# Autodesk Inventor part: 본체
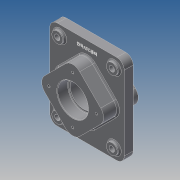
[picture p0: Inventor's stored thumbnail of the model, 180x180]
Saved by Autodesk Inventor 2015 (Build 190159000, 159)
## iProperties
Created: 2026-07
Part Number: 본체
Material: 일반
Document SubType Name: Modeling
Designer: USER
Density: 1 g/cm^3
Appearance: 기본값
Author: USER
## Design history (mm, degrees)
sketch "스케치1"
  geometry: L1 (75, 90)-(-75, 90); L2 (-75, 90)-(-75, -90); L3 (-75, -90)-(75, -90); L4 (75, -90)-(75, 90); L5 (75, 90)-(-75, -90); L6 (-75, 90)-(75, -90); 1 further point
  constraints: 12 end point, 2 midpoint, 2 parallel, 1 horizontal, 1 perpendicular
  dimensions: "d0" = 150 distance of L3.end L2.end; "d1" = 180 distance of L2.end L1.end
extrude "돌출1" new body sketch "스케치1" distance "d2" = 18; taper "d3" = 0 deg
sketch "스케치2"
  geometry: L1 (0, -70.711)-(-70.711, 0); L2 (-70.711, 0)-(0, 70.711); L3 (0, 70.711)-(70.711, 0); L4 (70.711, 0)-(0, -70.711); 2 further points
  constraints: 8 end point, 2 horizontal alignment, 1 coincident, 1 vertical alignment, 9 other
  dimensions: "d4" = 100 distance between parallel lines of L1 L3
extrude "돌출2" join sketch "스케치2" distance "d5" = 29; taper "d6" = 0 deg
sketch "스케치3"
  geometry: L1 (0, 70.711)-(70.711, 0); L2 (70.711, 0)-(0, -70.711); L3 (0, -70.711)-(-70.711, 0); L4 (-70.711, 0)-(0, 70.711); 2 further points
  constraints: 8 end point, 2 horizontal alignment, 2 vertical alignment, 1 coincident, 9 other
  dimensions: "d7" = 100 distance between parallel lines of L3 L1
extrude "돌출3" join sketch "스케치3" distance "d8" = 23; taper "d9" = 0 deg
fillet "모깎기1" dims "d10" = 15
fillet "모깎기2" dims "d11" = 20
fillet "모깎기3" dims "d12" = 20
hole "구멍1" diameter "d15" = 54; stored, may be unused: countersink angle "d19" = 90 deg, drill point angle "d21" = 0 deg; dims "d13" = 50, "d14" = 50, "d16" = 6, "d17" = 62, "d18" = 22, "d20" = 8
hole "구멍2" diameter "d24" = 62; stored, may be unused: countersink angle "d28" = 90 deg, drill point angle "d30" = 0 deg; dims "d22" = 50, "d23" = 50, "d25" = 6, "d26" = 62, "d27" = 22, "d29" = 22
sketch "스케치4"
  geometry: L1 (0, 0)-(0, 48)
  constraints: 2 end point, 1 vertical
  dimensions: "d31" = 48 distance of L1.start L1.end
hole "구멍3" sketch "스케치4" at (0, 48) diameter "d32" = 4.917; stored, may be unused: countersink angle "d36" = 90 deg, drill point angle "d38" = 118 deg; dims "d33" = 10, "d34" = 62, "d35" = 22, "d37" = 13
sketch "스케치5"
  geometry: L1 (0, 0)-(0, -48); C1 r 2.458 at (0, -48) reference
  constraints: 2 end point, 1 vertical
  dimensions: "d42" = 48 distance of L1.start L1.end (derived)
hole "구멍4" sketch "스케치5" at (0, -48) diameter "d43" = 4.917; stored, may be unused: countersink angle "d47" = 90 deg, drill point angle "d49" = 118 deg; dims "d44" = 10, "d45" = 62, "d46" = 22, "d48" = 13
sketch "스케치6"
  geometry: L1 (-75, -75)-(-75, 75) reference; L2 (-60, 90)-(60, 90) reference; L3 (75, 75)-(75, -75) reference; L4 (60, -90)-(-60, -90) reference; L5 (56.569, 14.142)-(14.142, 56.569) reference; L6 (-14.142, 56.569)-(-56.569, 14.142) reference; L7 (-56.569, -14.142)-(-14.142, -56.569) reference; L8 (14.142, -56.569)-(56.569, -14.142) reference; L9 (56.569, -14.142)-(14.142, -56.569) reference; L10 (-14.142, -56.569)-(-56.569, -14.142) reference; L11 (-56.569, 14.142)-(-14.142, 56.569) reference; L12 (14.142, 56.569)-(56.569, 14.142) reference; L13 (60, -90)-(-60, -90) reference; L14 (-75, -75)-(-75, 75) reference; L15 (-60, 90)-(60, 90) reference; L16 (75, 75)-(75, -75) reference; C1 r 27 at (0, 0) reference; C2 r 11 at (-55, 70); A1 r 15 centre (-60, -75) between (-75, -75) and (-60, -90) reference; A2 r 15 centre (-60, 75) between (-60, 90) and (-75, 75) reference; A3 r 15 centre (60, 75) between (75, 75) and (60, 90) reference; A4 r 15 centre (60, -75) between (60, -90) and (75, -75) reference; A5 r 20 centre (0, 42.426) between (14.142, 56.569) and (-14.142, 56.569) reference; A6 r 20 centre (-42.426, 0) between (-56.569, 14.142) and (-56.569, -14.142) reference; A7 r 20 centre (0, -42.426) between (-14.142, -56.569) and (14.142, -56.569) reference; A8 r 20 centre (42.426, 0) between (56.569, -14.142) and (56.569, 14.142) reference; A9 r 20 centre (42.426, 0) between (56.569, -14.142) and (56.569, 14.142) reference; A10 r 20 centre (0, -42.426) between (-14.142, -56.569) and (14.142, -56.569) reference; A11 r 20 centre (-42.426, 0) between (-56.569, 14.142) and (-56.569, -14.142) reference; A12 r 20 centre (0, 42.426) between (14.142, 56.569) and (-14.142, 56.569) reference; A13 r 15 centre (60, -75) between (60, -90) and (75, -75) reference; A14 r 15 centre (-60, -75) between (-75, -75) and (-60, -90) reference; A15 r 15 centre (-60, 75) between (-60, 90) and (-75, 75) reference; A16 r 15 centre (60, 75) between (75, 75) and (60, 90) reference; 1 further point
  constraints: 1 centre point
  dimensions: "d53" = 22 diameter of C2; "d54" = 55 horizontal distance of C2.centre point (0, 0); "d55" = 70 vertical distance of point (0, 0) C2.centre
extrude "돌출4" join sketch "스케치6" distance "d56" = 5; taper "d57" = 0 deg
hole "구멍5" diameter "d60" = 11; stored, may be unused: countersink angle "d64" = 90 deg, drill point angle "d66" = 0 deg; dims "d58" = 10, "d59" = 10, "d61" = 6, "d62" = 4, "d63" = 2, "d65" = 8
sketch "스케치7"
  geometry: L1 (-60, 90)-(60, 90) reference; 2 further points
  constraints: 1 vertical alignment, 1 other
  dimensions: "d73" = 15 distance from line of point (0, 75) L1
feature "엠보싱1" sketch "스케치7" dims "d0" = 150, "d1" = 180, "d7" = 100, "d74" = 0.5, "d75" = 0
chamfer "모따기1" distance "d76" = 1; stored, may be unused: second distance "d77" = 2, angle "d78" = 45 deg
fillet "모깎기4" dims "d79" = 1
fillet "모깎기5" dims "d80" = 3
fillet "모깎기6" dims "d81" = 3
fillet "모깎기7" dims "d82" = 3
node "솔리드1"
pattern_circular "원형 패턴1" dims angle "d40" = 360 deg
pattern_circular "원형 패턴2" dims angle "d51" = 360 deg
pattern_linear "직사각형 패턴1"
node "투영된 루프1"
node "절단 모서리 투영1"
